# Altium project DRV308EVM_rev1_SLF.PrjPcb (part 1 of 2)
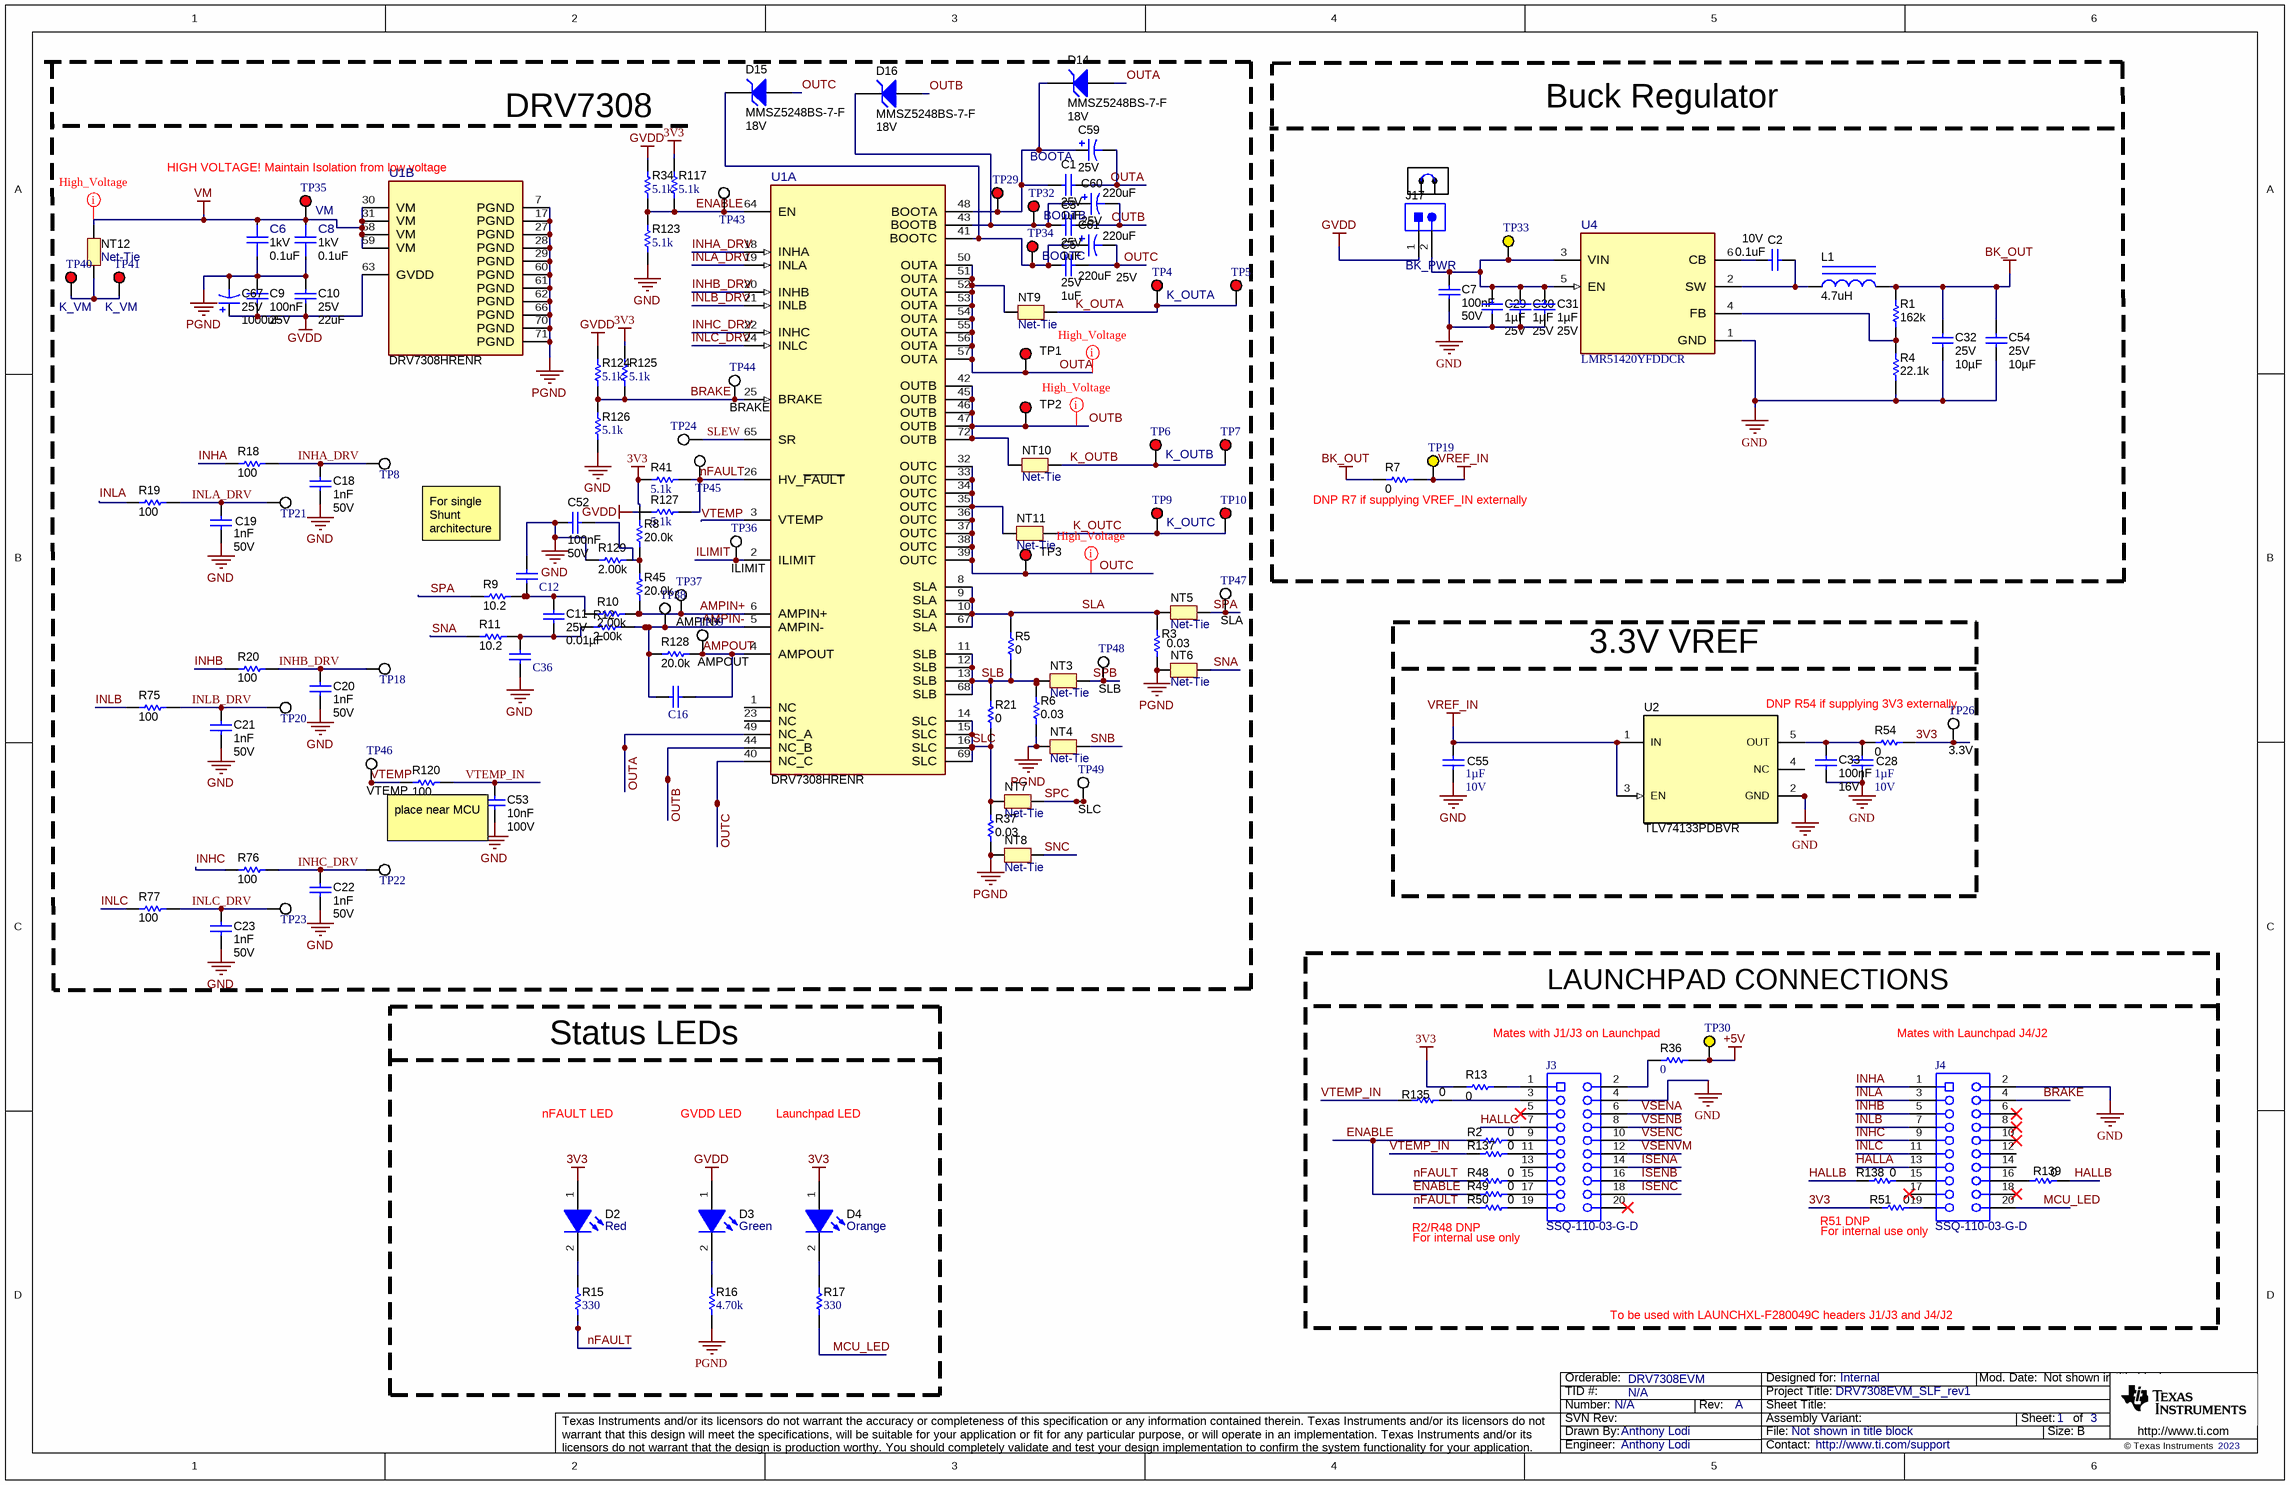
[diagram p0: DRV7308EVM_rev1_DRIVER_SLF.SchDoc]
CopyrightYear: 2023; DrawnBy: Anthony Lodi; EVM_orderable: DRV7308EVM; PCB_Layout: Anthony Lodi; PCB_Rev: A; PRJ_Customer: Internal; PRJ_Engineer: Anthony Lodi; PRJ_Number: N/A; PRJ_Title: DRV7308EVM_SLF_rev1; ProjectVariant: DRV7308EVM_rev1; SCH_Rev: A; TechSupport: http://www.ti.com/support; TID: N/A
3 sheets, 307 parts. Net scope: global (net labels, ports and power ports of the same name join across sheets).
Board file: DRV7308EVM_rev1_SLF.PcbDoc
Sheets:
  DRV7308EVM_rev1_DRIVER_SLF.SchDoc
  DRV7308EVM_rev1_HARDWARE_SLF.SchDoc
  DRV7308EVM_rev1_POWER_AND_CONNECTORS_SLF.SchDoc

## Sheet DRV7308EVM_rev1_DRIVER_SLF.SchDoc
size 431 x 279 mm; Date: Not shown in title block; ApprovedBy: Not shown in title block; CheckedBy: Not shown in title block; Author: Not shown in title block; CompanyName: Not shown in title block; DrawnBy: Anthony Lodi; Engineer: Not shown in title block; Organization: Not shown in title block; Address1: Not shown in title block; Address2: Not shown in title block; Address3: Not shown in title block; Address4: Not shown in title block; DocumentNumber: 1; Revision: Use project parameter SCH_Rev; SheetNumber: 1; SheetTotal: 3; PageSetup: Record=PageOptions¦CenterHorizontal=True¦CenterVertical=True¦PrintScale=1.00¦XCorrection=1.00¦YCorrection=1.00¦PrintKind=0¦BorderSize=5000000¦LeftOffset=0¦BottomOffset=0¦Orientation=2¦PaperLength=1000¦PaperWidth=1000¦Scale=100¦PaperSource=15¦PrintQuality=600¦MediaType=1¦DitherType=10¦PaperKind=Letter¦PrintScaleMode=1

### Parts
C1  VDC_V: 25V  ValueDisplayed: 1uF  [1206L]  (hidden comment: 12063C105KAT2A)
C2  VDC_V: 10V  ValueDisplayed: 0.1uF  [0402L]  (hidden comment: CL05B104KP5NNNC)
C3  VDC_V: 25V  ValueDisplayed: 1uF  [1206L]  (hidden comment: 12063C105KAT2A)
C5  VDC_V: 25V  ValueDisplayed: 1uF  [1206L]  (hidden comment: 12063C105KAT2A)
C6  VDC_V: 1kV  ValueDisplayed: 0.1uF  [FP-VJ2225Y104KXGAT_2225-IPC_A]  (hidden comment: VJ2225Y104KXGAT)
C7  Cap_F: 100nF  VDC_V: 50V  [0603L]  (hidden comment: 885012206095)
C8  VDC_V: 1kV  ValueDisplayed: 0.1uF  [FP-VJ2225Y104KXGAT_2225-IPC_A]  (hidden comment: VJ2225Y104KXGAT)
C9  Cap_F: 100nF  VDC_V: 25V  [0805_HV]  (hidden comment: 08053C104KAT2A)
C10  VDC_V: 25V  ValueDisplayed: 22uF  [1210_270L]  (hidden comment: GRM32ER71E226KE15L)
C11  VDC_V: 25V  ValueDisplayed: 0.01µF  [0402L]  (hidden comment: CL05B103KA5NNNC)
C12  885012206003  [WCAP-CSGP_0603_L1.6W0.8H0.8_Reflow]  (value not drawn)
C16  885012206003  [WCAP-CSGP_0603_L1.6W0.8H0.8_Reflow]  (value not drawn)
C18  Cap_F: 1nF  VDC_V: 50V  [0603L]  (hidden comment: 885012206083)
C19  Cap_F: 1nF  VDC_V: 50V  [0603L]  (hidden comment: 885012206083)
C20  Cap_F: 1nF  VDC_V: 50V  [0603L]  (hidden comment: 885012206083)
C21  Cap_F: 1nF  VDC_V: 50V  [0603L]  (hidden comment: 885012206083)
C22  Cap_F: 1nF  VDC_V: 50V  [0603L]  (hidden comment: 885012206083)
C23  Cap_F: 1nF  VDC_V: 50V  [0603L]  (hidden comment: 885012206083)
C28  Cap_F: 1µF  VDC_V: 10V  [0603L]  (hidden comment: LMK107B7105KAHT)
C29  Cap_F: 1µF  VDC_V: 25V  [0603L]  (hidden comment: CGA3E1X7R1E105K080AC)
C30  Cap_F: 1µF  VDC_V: 25V  [0603L]  (hidden comment: CGA3E1X7R1E105K080AC)
C31  Cap_F: 1µF  VDC_V: 25V  [0603L]  (hidden comment: CGA3E1X7R1E105K080AC)
C32  VDC_V: 25V  ValueDisplayed: 10µF  [1206_180L]  (hidden comment: C3216X7R1E106K160AB)
C33  Cap_F: 100nF  VDC_V: 16V  [0603L]  (hidden comment: EMK107B7104KA-T)
C36  885012206003  [WCAP-CSGP_0603_L1.6W0.8H0.8_Reflow]  (value not drawn)
C52  Cap_F: 100nF  VDC_V: 50V  [0603L]  (hidden comment: 885012206095)
C53  Cap_F: 10nF  VDC_V: 100V  [0603L]  (hidden comment: 06031C103JAT2A)
C54  VDC_V: 25V  ValueDisplayed: 10µF  [1206_180L]  (hidden comment: C3216X7R1E106K160AB)
C55  Cap_F: 1µF  VDC_V: 10V  [0603L]  (hidden comment: LMK107B7105KAHT)
C59  VDC_V: 25V  ValueDisplayed: 220uF  [BT_1000x1250]  (hidden comment: UBT1E221MPD1TD)
C60  VDC_V: 25V  ValueDisplayed: 220uF  [BT_1000x1250]  (hidden comment: UBT1E221MPD1TD)
C61  VDC_V: 25V  ValueDisplayed: 220uF  [BT_1000x1250]  (hidden comment: UBT1E221MPD1TD)
C67  VDC_V: 25V  ValueDisplayed: 1000uF  [Chemi-Con_1000x2000]  (hidden comment: EKMG250ELL102MJ20S)
D2  value Red  [LED_LTST-C170_Red]  (hidden comment: LTST-C170KRKT)
D3  value Green  [LTST-C170KGKT_Green]  (hidden comment: GVDD_LED)
D4  value Orange  [LTST-C170KFKT_Orange]  (hidden comment: MCU_LED)
D14  MMSZ5248BS-7-F  value 18V  [SOD-323]
D15  MMSZ5248BS-7-F  value 18V  [SOD-323]
D16  MMSZ5248BS-7-F  value 18V  [SOD-323]
J3  SSQ-110-03-G-D  [Samtec_SSQ-110-03-x-D]
J4  SSQ-110-03-G-D  [Samtec_SSQ-110-03-x-D]
J17  BK_PWR  [TSW-102-07-G-S]
L1  ValueDisplayed: 4.7uH  [WE-MAIA_3015]  (hidden comment: 78438335047)
NT3  Net-Tie  [Net-Tie_10mil]  (net tie, no BOM)
NT4  Net-Tie  [Net-Tie_10mil]  (net tie, no BOM)
NT5  Net-Tie  [Net-Tie_10mil]  (net tie, no BOM)
NT6  Net-Tie  [Net-Tie_10mil]  (net tie, no BOM)
NT7  Net-Tie  [Net-Tie_10mil]  (net tie, no BOM)
NT8  Net-Tie  [Net-Tie_10mil]  (net tie, no BOM)
NT9  Net-Tie  [Net-Tie_10milWide_30milLong]  (net tie, no BOM)
NT10  Net-Tie  [Net-Tie_10milWide_30milLong]  (net tie, no BOM)
NT11  Net-Tie  [Net-Tie_10milWide_30milLong]  (net tie, no BOM)
NT12  Net-Tie  [Net-Tie_10milWide_30milLong]  (net tie, no BOM)
R1  ValueDisplayed: 162k  [0603L]  (hidden comment: CRCW0603162KFKEA)
R2  ValueDisplayed: 0  [0603L]  (hidden comment: ERJ-3GEY0R00V)
R3  ValueDisplayed: 0.03  [1206L]  (hidden comment: CSR1206FK30L0)
R4  ValueDisplayed: 22.1k  [0603L]  (hidden comment: RT0603DRE0722K1L)
R5  ValueDisplayed: 0  [0805L]  (hidden comment: ERJ-6GEY0R00V)
R6  ValueDisplayed: 0.03  [1206L]  (hidden comment: CSR1206FK30L0)
R7  ValueDisplayed: 0  [0805L]  (hidden comment: ERJ-6GEY0R00V)
R8  ValueDisplayed: 20.0k  [0402L]  (hidden comment: CRCW040220K0FKED)
R9  ValueDisplayed: 10.2  [0402L]  (hidden comment: CRCW040210R2FKED)
R10  ValueDisplayed: 2.00k  [0402L]  (hidden comment: ERJ-2RKF2001X)
R11  ValueDisplayed: 10.2  [0402L]  (hidden comment: CRCW040210R2FKED)
R12  ValueDisplayed: 2.00k  [0402L]  (hidden comment: ERJ-2RKF2001X)
R13  ValueDisplayed: 0  [0805L]  (hidden comment: ERJ-6GEY0R00V)
R15  ValueDisplayed: 330  [0603L]  (hidden comment: ERA3AEB331V)
R16  ValueDisplayed: 4.70k  [0603L]  (hidden comment: RT0603BRD074K7L)
R17  ValueDisplayed: 330  [0603L]  (hidden comment: ERA3AEB331V)
R18  ValueDisplayed: 100  [0603L]  (hidden comment: RC0603FR-07100RL)
R19  ValueDisplayed: 100  [0603L]  (hidden comment: RC0603FR-07100RL)
R20  ValueDisplayed: 100  [0603L]  (hidden comment: RC0603FR-07100RL)
R21  ValueDisplayed: 0  [0805L]  (hidden comment: ERJ-6GEY0R00V)
R34  ValueDisplayed: 5.1k  [0603L]  (hidden comment: CRCW06035K10JNEA)
R36  ValueDisplayed: 0  [0805L]  (hidden comment: ERJ-6GEY0R00V)
R37  ValueDisplayed: 0.03  [1206L]  (hidden comment: CSR1206FK30L0)
R41  ValueDisplayed: 5.1k  [0603L]  (hidden comment: CRCW06035K10JNEA)
R45  ValueDisplayed: 20.0k  [0402L]  (hidden comment: CRCW040220K0FKED)
R48  ValueDisplayed: 0  [0603L]  (hidden comment: ERJ-3GEY0R00V)
R49  ValueDisplayed: 0  [0603L]  (hidden comment: ERJ-3GEY0R00V)
R50  ValueDisplayed: 0  [0603L]  (hidden comment: ERJ-3GEY0R00V)
R51  ValueDisplayed: 0  [0603L]  (hidden comment: ERJ-3GEY0R00V)
R54  ValueDisplayed: 0  [0603L]  (hidden comment: ERJ-3GEY0R00V)
R75  ValueDisplayed: 100  [0603L]  (hidden comment: RC0603FR-07100RL)
R76  ValueDisplayed: 100  [0603L]  (hidden comment: RC0603FR-07100RL)
R77  ValueDisplayed: 100  [0603L]  (hidden comment: RC0603FR-07100RL)
R117  ValueDisplayed: 5.1k  [0603L]  (hidden comment: CRCW06035K10JNEA)
R120  ValueDisplayed: 100  [0603L]  (hidden comment: RC0603FR-07100RL)
R123  ValueDisplayed: 5.1k  [0603L]  (hidden comment: CRCW06035K10JNEA)
R124  ValueDisplayed: 5.1k  [0603L]  (hidden comment: CRCW06035K10JNEA)
R125  ValueDisplayed: 5.1k  [0603L]  (hidden comment: CRCW06035K10JNEA)
R126  ValueDisplayed: 5.1k  [0603L]  (hidden comment: CRCW06035K10JNEA)
R127  ValueDisplayed: 5.1k  [0603L]  (hidden comment: CRCW06035K10JNEA)
R128  ValueDisplayed: 20.0k  [0402L]  (hidden comment: CRCW040220K0FKED)
R129  ValueDisplayed: 2.00k  [0402L]  (hidden comment: ERJ-2RKF2001X)
R135  ValueDisplayed: 0  [0603L]  (hidden comment: ERJ-3GEY0R00V)
R137  ValueDisplayed: 0  [0603L]  (hidden comment: ERJ-3GEY0R00V)
R138  ValueDisplayed: 0  [0603L]  (hidden comment: ERJ-3GEY0R00V)
R139  ValueDisplayed: 0  [0603L]  (hidden comment: ERJ-3GEY0R00V)
SH-J2  SNT-100-BK-G  [SNT-100-BK-G]  (value not drawn)
TP1  OUTA  [Keystone5000]  (value not drawn)
TP2  OUTB  [Keystone5000]  (value not drawn)
TP3  OUTC  [Keystone5000]  (value not drawn)
TP4  K_OUTA  [Keystone5000]
TP5  K_LS_D  [Keystone5000]  (value not drawn)
TP6  K_OUTB  [Keystone5000]
TP7  K_OUTB  [Keystone5000]  (value not drawn)
TP8  INHA  [Testpoint_Keystone_Miniature]  (value not drawn)
TP9  K_OUTC  [Keystone5000]
TP10  K_LS_D  [Keystone5000]  (value not drawn)
TP18  INHB  [Testpoint_Keystone_Miniature]  (value not drawn)
TP19  LDO_IN  [Keystone5009]  (value not drawn)
TP20  INLB  [Testpoint_Keystone_Miniature]  (value not drawn)
TP21  INLA  [Testpoint_Keystone_Miniature]  (value not drawn)
TP22  INHC  [Testpoint_Keystone_Miniature]  (value not drawn)
TP23  INLC  [Testpoint_Keystone_Miniature]  (value not drawn)
TP24  SLEW  [Testpoint_Keystone_Miniature]  (value not drawn)
TP26  3.3V  [Keystone5002]
TP29  BOOTA  [Keystone5000]
TP30  +5V  [Keystone5009]  (value not drawn)
TP32  BOOTB  [Keystone5000]
TP33  BK_PWR  [Keystone5009]  (value not drawn)
TP34  BOOTC  [Keystone5000]
TP35  VM  [Keystone5000]
TP36  ILIMIT  [Keystone5002]
TP37  AMPIN+  [Keystone5002]
TP38  AMPIN-  [Keystone5002]  (value not drawn)
TP39  AMPOUT  [Keystone5002]
TP40  K_VM  [Keystone5000]
TP41  K_VM  [Keystone5000]
TP43  ENABLE  [Testpoint_Keystone_Miniature]  (value not drawn)
TP44  BRAKE  [Keystone5002]
TP45  nFAULT  [Testpoint_Keystone_Miniature]  (value not drawn)
TP46  VTEMP  [Keystone5002]
TP47  SLA  [Keystone5002]
TP48  SLB  [Keystone5002]
TP49  SLC  [Keystone5002]
U1  DRV7308HRENR  [REN0065A-MFG]  (parts A,B of 2)
U2  TLV74133PDBVR  [DBV0005A_N]
U4  LMR51420YFDDCR  [DDC0006A-MFG]

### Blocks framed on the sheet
Buck Regulator: C2 C7 C29-C32 C54 J17 L1 R1 R4 R7 SH-J2 TP19 TP33 U4
3.3V VREF: C28 C33 C55 R54 TP26 U2
LAUNCHPAD CONNECTIONS: J3 J4 R2 R13 R36 R48-R51 R135 R137-R139 TP30
Status LEDs: D2-D4 R15-R17

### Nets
3V3: D2.1(A) D4.1(A) R8.2 R13.1 R41.2 R51.1 R54.2 R117.1 R125.1 TP26.1
+5V: R36.2 TP30.1
BK_OUT: C32.1 C54.1 L1.2 R1.2 R7.1
GND: C7.2 C12.1 C18.2 C19.2 C20.2 C21.2 C22.2 C23.2 C28.2 C29.2 C30.2 C31.2 C32.2 C33.2 C36.2 C52.1 C53.2 C54.2 C55.2 J3.4 J4.2 R4.1 R123.1 R126.1 R129.1 U2.2(GND) U4.1(GND)
GVDD: C9.2 C10.2 C67.1(+) D3.1(A) J17.1 R34.1 R124.1 R127.1 U1.63(GVDD)
PGND: C6.1 C8.1 C9.1 C10.1 C67.2(-) NT4.1 NT6.1 NT8.1 R3.1 R6.1 R16.1 R37.1 U1.7(PGND) U1.17(PGND) U1.27(PGND) U1.28(PGND) U1.29(PGND) U1.60(PGND) U1.61(PGND) U1.62(PGND) U1.66(PGND) U1.70(PGND) U1.71(PGND)
VM: C6.2 C8.2 NT12.2 TP35.1 U1.30(VM) U1.31(VM) U1.58(VM) U1.59(VM)
VREF_IN: C55.1 R7.2 TP19.1 U2.1(IN) U2.3(EN)
AMPIN+: R10.2 R45.1 TP37.1 U1.6(AMPIN+)
AMPIN-: C16.1 R12.2 R128.1 TP38.1 U1.5(AMPIN-)
AMPOUT: C16.2 R128.2 TP39.1 U1.4(AMPOUT)
BRAKE: J4.4 R124.2 R125.2 R126.2 TP44.1 U1.25(BRAKE)
ENABLE: R2.1 R34.2 R49.1 R117.2 R123.2 TP43.1 U1.64(EN)
HALLA: J4.13
HALLB: R138.1 R139.2
HALLC: J3.7
ILIMIT: TP36.1 U1.2(ILIMIT)
INHA: J4.1 R18.1
INHA_DRV: C18.1 R18.2 TP8.1 U1.18(INHA)
INHB: J4.5 R20.1
INHB_DRV: C20.1 R20.2 TP18.1 U1.20(INHB)
INHC: J4.9 R76.1
INHC_DRV: C22.1 R76.2 TP22.1 U1.22(INHC)
INLA: J4.3 R19.1
INLA_DRV: C19.1 R19.2 TP21.1 U1.19(INLA)
INLB: J4.7 R75.1
INLB_DRV: C21.1 R75.2 TP20.1 U1.21(INLB)
INLC: J4.11 R77.1
INLC_DRV: C23.1 R77.2 TP23.1 U1.24(INLC)
ISENA: J3.14
ISENB: J3.16
ISENC: J3.18
K_OUTA: NT9.2 TP4.1 TP5.1
K_OUTB: NT10.2 TP6.1 TP7.1
K_OUTC: NT11.2 TP9.1 TP10.1
MCU_LED: J4.20 R17.1
nFAULT: R15.1 R41.1 R48.1 R50.1 R127.2 TP45.1 U1.26(HV_~{FAULT})
OUTA: C1.1 C59.2(-) D14.2(A) NT9.1 TP1.1 U1.49(NC_A) U1.50(OUTA) U1.51(OUTA) U1.52(OUTA) U1.53(OUTA) U1.54(OUTA) U1.55(OUTA) U1.56(OUTA) U1.57(OUTA)
OUTB: C3.1 C60.2(-) D16.2(A) NT10.1 TP2.1 U1.42(OUTB) U1.44(NC_B) U1.45(OUTB) U1.46(OUTB) U1.47(OUTB) U1.72(OUTB)
OUTC: C5.1 C61.2(-) D15.2(A) NT11.1 TP3.1 U1.32(OUTC) U1.33(OUTC) U1.34(OUTC) U1.35(OUTC) U1.36(OUTC) U1.37(OUTC) U1.38(OUTC) U1.39(OUTC) U1.40(NC_C)
SLA: NT5.1 R3.2 R5.2 U1.8(SLA) U1.9(SLA) U1.10(SLA) U1.67(SLA)
SLB: NT3.1 R5.1 R6.2 R21.2 U1.11(SLB) U1.12(SLB) U1.13(SLB) U1.68(SLB)
SLC: NT7.1 R21.1 R37.2 U1.14(SLC) U1.15(SLC) U1.16(SLC) U1.69(SLC)
SLEW: TP24.1 U1.65(SR)
SNA: NT6.2 R11.1
SNB: NT4.2
SNC: NT8.2
SPA: NT5.2 R9.1 TP47.1
SPB: NT3.2 TP48.1
SPC: NT7.2 TP49.1
VSENA: J3.6
VSENB: J3.8
VSENC: J3.10
VSENVM: J3.12
VTEMP: R120.1 TP46.1 U1.3(VTEMP)
VTEMP_IN: C53.1 R120.2 R135.1 R137.1
NetC1_2: C1.2 C59.1(+) D14.1(K) TP29.1 U1.48(BOOTA)
NetC2_1: C2.1 L1.1 U4.2(SW)
NetC2_2: C2.2 U4.6(CB)
NetC3_2: C3.2 C60.1(+) D16.1(K) TP32.1 U1.43(BOOTB)
NetC5_2: C5.2 C61.1(+) D15.1(K) TP34.1 U1.41(BOOTC)
NetC7_1: C7.1 C29.1 C30.1 C31.1 J17.2 TP33.1 U4.3(VIN) U4.5(EN)
NetC11_1: C11.1 C12.2 R9.2 R10.1
NetC11_2: C11.2 C36.1 R11.2 R12.1
NetC28_1: C28.1 C33.1 R54.1 U2.5(OUT)
NetC52_2: C52.2 R8.1 R45.2 R129.2
NetD2_2: D2.2(K) R15.2
NetD3_2: D3.2(K) R16.2
NetD4_2: D4.2(K) R17.2
NetJ3_1: J3.1 R13.2
NetJ3_2: J3.2 R36.1
NetJ3_3: J3.3 R135.2
NetJ3_9: J3.9 R2.2
NetJ3_11: J3.11 R137.2
NetJ3_15: J3.15 R48.2
NetJ3_17: J3.17 R49.2
NetJ3_19: J3.19 R50.2
NetJ4_15: J4.15 R138.2
NetJ4_16: J4.16 R139.1
NetJ4_19: J4.19 R51.2
NetNT12_1: NT12.1 TP40.1 TP41.1
NetR1_1: R1.1 R4.2 U4.4(FB)

Not connected (* = marked no-connect by the designer): J3 5* 13 20*; J4 6* 8* 10* 12 14 17* 18*; U1 1(NC) 23(NC); U2 4(NC)

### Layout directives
net class High_Voltage: (no net found under the mark), OUTA, OUTC, VM

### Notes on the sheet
- HIGH VOLTAGE! Maintain Isolation from low voltage
- DRV7308
- (near R7) DNP R7 if supplying VREF_IN externally
- For single Shunt architecture
- DNP R54 if supplying 3V3 externally
- place near MCU
- (near R36) Mates with J1/J3 on Launchpad
- (near J4) Mates with Launchpad J4/J2
- nFAULT LED
- GVDD LED
- Launchpad LED
- (near R50) R2/R48 DNP
- For internal use only
- (near R51) R51 DNP
- To be used with LAUNCHXL-F280049C headers J1/J3 and J4/J2

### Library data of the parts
C1 C3 C5 = CMP-0008509-2: CAP, CERM, 1 uF, 25 V, +/- 10%, X7R, 1206; Manufacturer: AVX; TaMin_C: -55°C; ESR_ohm: 13m; Polarized: N; SizeAreaWB_mm2: 10.92; Value1: 0.013 ohm; U/M: EA; Value: 1uF; TaMax_C: 125°C; SizeZ_mm: 1.35; SizeX_mm: 3.2; SizeY_mm: 1.6; Cap_Case: 1206; SizeArea_mm2: 5.12; Cap_F: 1µF; AEC Category: Q200
C2 = CMP-0006343-2: CAP, CERM, 0.1 uF, 10 V, +/- 10%, X7R, 0402; Manufacturer: Samsung Electro-Mechanics; TaMin_C: -55°C; Polarized: N; SizeAreaWB_mm2: 3; Value1: Unknown; U/M: EA; Value: 0.1uF; TaMax_C: 125°C; SizeZ_mm: 0.6; SizeX_mm: 1; SizeY_mm: 0.5; Cap_Case: 0402; Cap_F: 100nF; AEC Category: Q200
C6 C8 = CMP-0097628-1: 2225 0.1 uF 1 kV ±10 % Tolerance X7R SMT Multilayer Ceramic Chip Capacitor; Manufacturer: Vishay Vitramon; Tolerance_%: 10%; Cap_F: 100nF; Value: 100nF; SizeZ_mm: 2.18mm; TempCo: 15%; AEC Qualified: No
C7 C52 = CMP-0006837-2: CAP, CERM, 0.1 uF, 50 V, +/- 10%, X7R, 0603; Manufacturer: Wurth Elektronik; TaMin_C: -55°C; Polarized: N; SizeAreaWB_mm2: 4.68; Value1: Unknown; U/M: EA; Value: 0.1uF; TaMax_C: 125°C; SizeZ_mm: 1; SizeX_mm: 1.6; SizeY_mm: 0.8; Cap_Case: 0603; SizeArea_mm2: 1.28; AEC Category: Q200
C9 = CMP-0007567-1: CAP, CERM, 0.1 uF, 25 V, +/- 10%, X7R, 0805; Manufacturer: AVX; TaMin_C: -55°C; ESR_ohm: 0.28; Polarized: N; SizeAreaWB_mm2: 6.75; Value1: 0.28 ohm; U/M: EA; Value: 0.1uF; TaMax_C: 125°C; SizeZ_mm: 1.45; SizeX_mm: 2; SizeY_mm: 1.25; Cap_Case: 0805; SizeArea_mm2: 2.5; AEC Category: Q200
C10 = CMP-0009224-2: CAP, CERM, 22 uF, 25 V, +/- 10%, X7R, 1210; Manufacturer: MuRata; TaMin_C: -55°C; Polarized: N; SizeAreaWB_mm2: 14.7; Value1: Unknown; U/M: EA; Value: 22uF; TaMax_C: 125°C; SizeZ_mm: 2.7; SizeX_mm: 3.2; SizeY_mm: 2.5; Cap_Case: 1210; SizeArea_mm2: 8; Cap_F: 22µF; AEC Category: Q200
C11 = CMP-0860561-1: CAP, CERM, 0.01 µF, 25 V,+/- 10%, X7R, 0402; Manufacturer: Samsung Electro-Mechanics; U/M: EA; SizeArea_mm2: 0.5; Value: 0.01uF; TaMin_C: -55°C; SizeZ_mm: 0.6; Polarized: N; SizeX_mm: 1; TaMax_C: 125°C; SizeAreaWB_mm2: 3; Cap_Case: 0402; Cap_F: 10nF; AEC Category: Q200
C12 C16 C36 = CMP-0104643-1: WCAP-CSGP Multilayer Ceramic Chip Capacitor, General Purpose, size 0603, X7R, 100pF, 10VDC; Manufacturer: Wurth Elektronik; Capacitance Tolerance: +/-10%; Case/Size Code: 0603; Dissipation Factor: 5%; Insulation Resistance: 10GOhm; Rated Voltage (DC): 10V; Technical Reference: X7R0603101K010DFCT10000
C18-C23 = CMP-0064933-2: CAP, CERM, 1000 pF, 50 V,+/- 10%, X7R, 0603; Manufacturer: Wurth Elektronik; TaMin_C: -55°C; Polarized: N; SizeAreaWB_mm2: 4.68; Value1: Unknown; U/M: EA; Value: 1000pF; TaMax_C: 125°C; SizeZ_mm: 1; SizeX_mm: 1.6; SizeY_mm: 0.8; Cap_Case: 0603; SizeArea_mm2: 1.28; AEC Category: Q200
C28 C55 = CMP-0007505-3: CAP, CERM, 1 uF, 10 V, +/- 10%, X7R, AEC-Q200 Grade 1, 0603; Manufacturer: Taiyo Yuden; TaMin_C: -55°C; Polarized: N; SizeAreaWB_mm2: 4.68; Value1: Unknown; U/M: EA; Value: 1uF; TaMax_C: 125°C; SizeZ_mm: 1; SizeX_mm: 1.6; SizeY_mm: 0.8; Cap_Case: 0603; SizeArea_mm2: 1.28; AEC Qualified: Y; AEC Category: Q200
C29-C31 = CMP-0076705-1: CAP, CERM, 1 µF, 25 V,+/- 10%, X7R, AEC-Q200 Grade 1, 0603; Manufacturer: TDK; SizeAreaWB_mm2: 4.68; SizeArea_mm2: 1.28; AEC Qualified: Y; AEC Category: Q200; Value: 1uF; TaMax_C: 125°C; SizeZ_mm: 1.0; AEC Grade: 1; Polarized: N; TaMin_C: -55°C; SizeY_mm: 0.8; U/M: EA; SizeX_mm: 1.6; Cap_Case: 1.6x0.8x0.8mm
C32 C54 = CMP-0080740-1: CAP, CERM, 10 µF, 25 V,+/- 10%, X7R, 1206; Manufacturer: TDK; SizeAreaWB_mm2: 10.92; SizeArea_mm2: 5.12; AEC Qualified: N; AEC Category: Q200; Value: 10uF; TaMax_C: 125°C; SizeZ_mm: 1.8; TaMin_C: -55°C; SizeY_mm: 1.6; U/M: EA; SizeX_mm: 3.2; Cap_Case: 1206
C33 = CMP-0007119-4: CAP, CERM, 0.1 uF, 16 V, +/- 10%, X7R, 0603; Manufacturer: Taiyo Yuden; TaMin_C: -55°C; Polarized: N; SizeAreaWB_mm2: 4.68; Value1: Unknown; U/M: EA; Value: 0.1uF; TaMax_C: 125°C; SizeZ_mm: 1; SizeX_mm: 1.6; SizeY_mm: 0.8; Cap_Case: 0603; SizeArea_mm2: 1.28; AEC Category: Q200
C53 = CMP-0006726-4: CAP, CERM, 0.01 uF, 100 V, +/- 5%, X7R, 0603; Manufacturer: AVX; TaMin_C: -55°C; ESR_ohm: 0.098; Polarized: N; SizeAreaWB_mm2: 4.68; Value1: 0.098 ohm; U/M: EA; Value: 0.01uF; TaMax_C: 125°C; SizeZ_mm: 1; SizeX_mm: 1.6; SizeY_mm: 0.8; Cap_Case: 0603; SizeArea_mm2: 1.28; AEC Category: Q200
C59-C61 = CMP-0010527-1: CAP, AL, 220 uF, 25 V, +/- 20%, 0.1 ohm, TH; Manufacturer: Nichicon; TaMin_C: -40°C; ESR_ohm: 0.1; Polarized: Y; SizeAreaWB_mm2: 144; Value1: 0.1 ohm; U/M: EA; Value: 220uF; TaMax_C: 125°C; SizeZ_mm: 14.5; SizeX_mm: 10; Cap_Case: 10x12.5mm; SizeArea_mm2: 100; CompType: Capacitor; Cap_F: 220µF; IRMS_A: 680mA; AEC Category: Q200
C67 = CMP-0010362-1: CAP, AL, 1000 uF, 25 V, +/- 20%, TH; Manufacturer: Chemi-Con; TaMin_C: -55°C; Polarized: Y; SizeAreaWB_mm2: 144; Value1: Unknown; U/M: EA; Value: 1000uF; TaMax_C: 105°C; SizeZ_mm: 21.5; SizeX_mm: 10; Cap_Case: 10x20mm; SizeArea_mm2: 100; CompType: Capacitor; AEC Qualified: N; Cap_F: 1mF; IRMS_A: 680mA; AEC Category: Q200
D2 = CMP-0002829-1: LED, Red, SMD; Manufacturer: Lite-On; Io_A: 20mA; SizeAreaWB_mm2: 6.75; Value1: W; U/M: EA; SizeZ_mm: 1.2; SizeX_mm: 2; SizeY_mm: 1.25; Vf_V: 2V; SizeArea_mm2: 2.5; Type: AlInGaP
D3 = CMP-0002888-1: LED, Green, SMD; Manufacturer: Lite-On; PartNumber: LTST-C170KGKT; Io_A: 20mA; Value1: W; U/M: EA; Vf_V: 2V; Type: AlInGaP
D4 = CMP-0002890-1: LED, Orange, SMD; Manufacturer: Lite-On; PartNumber: LTST-C170KFKT; Io_A: 20mA; Value1: W; U/M: EA; Vf_V: 2V; Type: AlInGaP
D14-D16 = CMP-0005835-4: Diode, Zener, 18 V, 200 mW, SOD-323; Manufacturer: Diodes Inc.; Value1: 0.2W; SizeArea_mm2: 3.645; AEC Category: Q101; Power_W: 200mW; SizeAreaWB_mm2: 8.695; SizeY_mm: 1.35; RJA_CperW: 350; SizeZ_mm: 1; SizeX_mm: 2.7
J3 J4 = CMP-0075613-1: Receptacle, 2.54mm, 10x2, Gold, TH; Manufacturer: Samtec; Pitch_mm: 2.54; Cert_VDE: N; Gender: Female; Cert_CSA: Y; Current_A: 6.3A; Voltage_V: 550V; CT: True; Row_Count: 2; CompType: Socket Strip; CNHeader: False
J17 = CMP-0075405-3: Header, 100mil, 2x1, Gold, TH; Manufacturer: Samtec; Current_A: 6.3A; Green_Lifecycle: Active; Pitch_mm: 2.54; Cert_CSA: Y; Cert_VDE: N; Green_REACh: Passed; Row_Count: 1; Gender: Male; Voltage_V: 550V
L1 = CMP-0064361-1: Inductor, Shielded, Powdered Iron, 4.7 uH, 1.5 A, 0.162 ohm, AEC-Q200 Grade 1, SMD; Manufacturer: Wurth Elektronik; Isat: 2.8A @ 20% inductance drop; Irms: 1.5A @ 40C rise; SizeAreaWB_mm2: 16; DCR_ohm: 0.162; Value: 4.7uH; Imax_A: 1.5A; SizeZ_mm: 1.5; SizeX_mm: 3; SizeArea_mm2: 9; Ind_H: 4.7µH; AEC Qualified: Y; AEC Grade: 1; AEC Category: Q200
NT3-NT12 = CMP-0078142-4: Single point connection between nets.
R1 = CMP-0022073-1: RES, 162 k, 1%, 0.1 W, 0603; Manufacturer: Vishay-Dale; Power_W: 100mW; TempCo: 100 ppm/C; U/M: EA; Value: 162k; EIA_Code: E96; SizeX_mm: 1.6; SizeY_mm: 0.8; SizeZ_mm: 1; Value2: 0.1W; SizeArea_mm2: 1.28; VDC_V: 75V; AEC Category: Q200
R2 R48-R51 R54 R135 R137-R139 = CMP-0025874-4: RES, 0, 5%, 0.1 W, AEC-Q200 Grade 0, 0603; Manufacturer: Panasonic; Power_W: 100mW; TempCo: 600 ppm/C; Value_Code: 0000; Value: 0; EIA_Code: E24; SizeX_mm: 1.6; SizeY_mm: 0.8; SizeZ_mm: 1; Value2: 0.1W; SizeArea_mm2: 1.28; AEC Qualified: Y; VDC_V: 50V; AEC Category: Q200; SizeAreaWB_mm2: 4.68
R3 R6 R37 = CMP-0017262-1: RES, 0.03, 1%, 0.5 W, 1206; Manufacturer: Stackpole Electronics Inc; Power_W: 500mW; TempCo: 100 ppm/C; Value_Code: R030; U/M: EA; Value: 0.03; EIA_Code: E96; SizeX_mm: 3.2; SizeY_mm: 1.6; SizeZ_mm: 1.35; Value2: 0.5W; SizeArea_mm2: 5.12; AEC Category: Q200
R4 = CMP-0024951-1: RES, 22.1 k, 0.5%, 0.1 W, 0603; Manufacturer: Yageo America; Power_W: 100mW; TempCo: 50 ppm/C; Value_Code: 22k1; U/M: EA; Value: 22.1k; EIA_Code: E192; SizeX_mm: 1.6; SizeY_mm: 0.8; SizeZ_mm: 1; Value2: 0.1W; SizeArea_mm2: 1.28; VDC_V: 75V; AEC Category: Q200
R5 R21 = CMP-0020616-1: RES, 0, 5%, 0.125 W, 0805; Manufacturer: Panasonic; Power_W: 125mW; TempCo: 600 ppm/C; Value_Code: 0000; U/M: EA; Value: 0; EIA_Code: E24; SizeX_mm: 2; SizeY_mm: 1.25; SizeZ_mm: 1.45; Value2: 0.125W; SizeArea_mm2: 2.5; VDC_V: 150V; AEC Category: Q200
R7 R13 R36 = CMP-0020616-3: RES, 0, 5%, 0.125 W, AEC-Q200 Grade 0, 0805; Manufacturer: Panasonic; Power_W: 125mW; TempCo: 600 ppm/C; Value_Code: 0000; Value: 0; EIA_Code: E24; SizeX_mm: 2; SizeY_mm: 1.25; SizeZ_mm: 1.45; Value2: 0.125W; SizeArea_mm2: 2.5; AEC Qualified: Y; VDC_V: 150V; AEC Category: Q200; SizeAreaWB_mm2: 6.75
R8 R45 R128 = CMP-0026162-2: RES, 20.0 k, 1%, 0.063 W, AEC-Q200 Grade 0, 0402; Manufacturer: Vishay-Dale; Power_W: 63mW; TempCo: 100 ppm/C; Value_Code: 20k0; Value: 20.0k; EIA_Code: E96; Res_ohm: 20k; SizeX_mm: 1; SizeY_mm: 0.5; SizeZ_mm: 0.6; Value2: 0.063W; AEC Qualified: Y; VDC_V: 50V; AEC Category: Q200; AEC Grade: 0
R9 R11 = CMP-0025964-3: RES, 10.2, 1%, 0.063 W, AEC-Q200 Grade 0, 0402; Manufacturer: Vishay-Dale; Power_W: 63mW; TempCo: 100 ppm/C; Value_Code: 10R2; Value: 10.2; EIA_Code: E96; SizeX_mm: 1; SizeY_mm: 0.5; SizeZ_mm: 0.6; Value2: 0.063W; AEC Qualified: Y; VDC_V: 50V; AEC Category: Q200; AEC Grade: 0
R10 R12 R129 = CMP-0026676-1: RES, 2.00 k, 1%, 0.1 W, AEC-Q200 Grade 0, 0402; Manufacturer: Panasonic; Power_W: 100mW; TempCo: 100 ppm/C; Value_Code: 2k00; U/M: EA; Value: 2.00k; EIA_Code: E96; Res_ohm: 2k; SizeX_mm: 1; SizeY_mm: 0.5; SizeZ_mm: 0.6; Value2: 0.1W; AEC Qualified: Y; VDC_V: 50V; AEC Grade: 0; AEC Category: Q200
R15 R17 = CMP-0078582-1: RES, 330, 0.1%, 0.1 W, AEC-Q200 Grade 0, 0603; Manufacturer: Panasonic; Power_W: 100mW; TempCo: 25 ppm/C; Value_Code: 330R; Value: 330; SizeX_mm: 1.6; SizeY_mm: 0.8; SizeZ_mm: 1; Value2: 0.1W; SizeArea_mm2: 1.28; AEC Qualified: Y; AEC Grade: 0; AEC Category: Q200
R16 = CMP-0024300-2: RES, 4.70 k, 0.1%, 0.1 W, 0603; Manufacturer: Yageo America; Power_W: 100mW; TempCo: 25 ppm/C; Value_Code: 4k70; U/M: EA; Value: 4.70k; EIA_Code: E192; Res_ohm: 4.7k; SizeX_mm: 1.6; SizeY_mm: 0.8; SizeZ_mm: 1; Value2: 0.1W; SizeArea_mm2: 1.28; VDC_V: 75V; AEC Category: Q200
R18-R20 R75-R77 R120 = CMP-0022736-4: RES, 100, 1%, 0.1 W, 0603; Manufacturer: Yageo; Power_W: 100mW; TempCo: 100 ppm/C; Value_Code: 100R; Value: 100; EIA_Code: E96; SizeX_mm: 1.6; SizeY_mm: 0.8; SizeZ_mm: 1; Value2: 0.1W; SizeArea_mm2: 1.28; AEC Qualified: N; VDC_V: 75V; AEC Category: Q200; SizeAreaWB_mm2: 4.68
R34 R41 R117 R123-R127 = CMP-0025830-1: RES, 5.1 k, 5%, 0.1 W, 0603; Manufacturer: Vishay-Dale; Power_W: 100mW; TempCo: 200 ppm/C; Value_Code: 5k10; U/M: EA; Value: 5.1k; EIA_Code: E24; SizeX_mm: 1.6; SizeY_mm: 0.8; SizeZ_mm: 1; Value2: 0.1W; SizeArea_mm2: 1.28; VDC_V: 75V; AEC Category: Q200
SH-J2 = CMP-0003623-3: Shunt, 100mil, Gold plated, Black; Alternate PartNumber: 969102-0000-DA; Manufacturer: Samtec; Alternate Manufacturer: 3M; Value: 1x2
TP1-TP3 = CMP-0055137-1: Test Point, Miniature, Red, TH; PartNumber: 5000; Manufacturer: Keystone; ContactFinish: Silver; CNHeader: FALSE; CT: TRUE; Green_Lifecycle: Active; Green_REACh: Passed
TP4-TP7 TP9 TP10 TP29 TP32 TP34 TP35 TP40 TP41 = CMP-0055137-2: Test Point, Miniature, Red, TH; Manufacturer: Keystone Electronics; Green_REACh: Passed; Green_Lifecycle: Active; ContactFinish: Silver; CNHeader: FALSE; CT: TRUE
TP8 TP18 TP20-TP24 TP43 TP45 = CMP-0055152-1: Test Point, Miniature, SMT; Manufacturer: Keystone; CNHeader: FALSE; Green_Lifecycle: Active; Green_REACh: Passed; CT: TRUE
TP19 TP30 TP33 = CMP-0055146-2: Test Point, Compact, Yellow, TH; Manufacturer: Keystone Electronics; Green_REACh: Passed; ContactFinish: Silver; CT: TRUE; CNHeader: FALSE; Green_Lifecycle: Active
TP26 TP36-TP39 TP44 TP46-TP49 = CMP-0055139-2: Test Point, Miniature, White, TH; Manufacturer: Keystone Electronics; ContactFinish: Silver; Green_REACh: Passed; CT: TRUE; Green_Lifecycle: Active; CNHeader: FALSE
U1 = CMP-0098388-1: Three-Phase, 650-V Integrated GaN FET Motor Driver, VQFN65; Manufacturer: Texas Instruments; SizeZ_mm: 1mm; AEC Qualified: No; Max Supply Voltage: 18.5V; Min Supply Voltage: 10.8V; Motor Type: Brushless DC; Nominal Supply Current: 1-5mA; Number Of Outputs: 3; Standoff Height: 0mm; Switching Frequency: 20kHz; TaMax_C: +100°C; TaMin_C: -40°C; TJmax_C: +125°C
U2 = CMP-0065093-2: Low-Dropout Regulator, DBV0005A (SOT-23-5); Manufacturer: Texas Instruments; SizeX_mm: 2.8; SizeY_mm: 2.9; CompType: IC; SizeZ_mm: 1.45; SizeArea_mm2: 8.12; SizeAreaWB_mm2: 14.82; U/M: EA
U4 = CMP-0094075-1: SIMPLE SWITCHER 4.5-V to 36-V, 2-A Buck Converter in SOT-23-6 Package; Manufacturer: Texas Instruments; Nominal Supply Current: 40-420uA; Output Voltage: 0.6-30.4V; TJmax_C: +150°C; Number Of Outputs: 1; Max Supply Voltage: 32V; Standoff Height: 0mm; AEC Qualified: No; Output Type: AdjustableProgrammable; SizeZ_mm: 1.1mm; Switching Frequency: 500kHz; Max Duty Cycle: 98%; Min Supply Voltage: 4.5V

## Sheet DRV7308EVM_rev1_HARDWARE_SLF.SchDoc
size 431 x 279 mm; Date: Not shown in title block; ApprovedBy: Not shown in title block; CheckedBy: Not shown in title block; Author: Not shown in title block; CompanyName: Not shown in title block; DrawnBy: Anthony Lodi; Engineer: Not shown in title block; Organization: Not shown in title block; Address1: Not shown in title block; Address2: Not shown in title block; Address3: Not shown in title block; Address4: Not shown in title block; DocumentNumber: 3; Revision: Use project parameter SCH_Rev; SheetNumber: 3; SheetTotal: 3; PageSetup: Record=PageOptions¦CenterHorizontal=True¦CenterVertical=True¦PrintScale=1.00¦XCorrection=1.00¦YCorrection=1.00¦PrintKind=0¦BorderSize=5000000¦LeftOffset=0¦BottomOffset=0¦Orientation=2¦PaperLength=1000¦PaperWidth=1000¦Scale=100¦PaperSource=15¦PrintQuality=600¦MediaType=1¦DitherType=10¦PaperKind=Letter¦PrintScaleMode=1
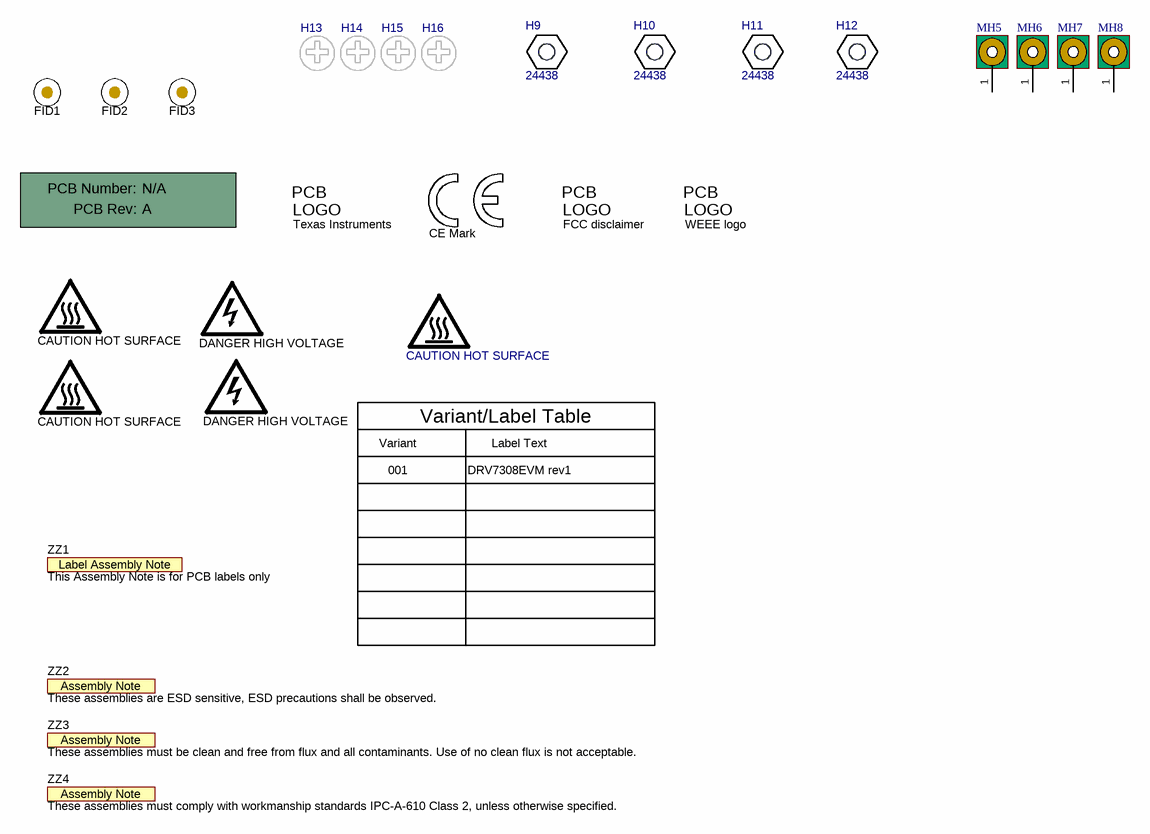
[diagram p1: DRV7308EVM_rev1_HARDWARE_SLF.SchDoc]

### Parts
!PCB1  Printed Circuit Board  (value not drawn)  (mechanical)
FID1  Fiducial  [Fiducial10-20]  (value not drawn)
FID2  Fiducial  [Fiducial10-20]  (value not drawn)
FID3  Fiducial  [Fiducial10-20]  (value not drawn)
H9  24438  [Keystone24438]
H10  24438  [Keystone24438]
H11  24438  [Keystone24438]
H12  24438  [Keystone24438]
H13  MPMS 003 0005 PH  [BuildingFastener_MPMS_003_0005_PH]  (value not drawn)
H14  MPMS 003 0005 PH  [BuildingFastener_MPMS_003_0005_PH]  (value not drawn)
H15  MPMS 003 0005 PH  [BuildingFastener_MPMS_003_0005_PH]  (value not drawn)
H16  MPMS 003 0005 PH  [BuildingFastener_MPMS_003_0005_PH]  (value not drawn)
LOGO  CAUTION HOT SURFACE  [IEC_HotSurface_Small]  (no BOM)
Logo1  CE Mark  [CE_Mark_5mm]  (no BOM)
Logo2  Texas Instruments  [TI_Stacked_Overlay_Small]  (no BOM)
Logo3  FCC disclaimer  [FCC_disclaimer]  (no BOM)
Logo4  WEEE logo  [WEEE_Minimum]  (no BOM)
LOGO5  CAUTION HOT SURFACE  [IEC_HotSurface_Small]  (no BOM)
LOGO6  DANGER HIGH VOLTAGE  [IEC_HighVoltage_Small]  (no BOM)
LOGO7  CAUTION HOT SURFACE  [IEC_HotSurface_Small]  (no BOM)
LOGO8  DANGER HIGH VOLTAGE  [IEC_HighVoltage_Small]  (no BOM)
MH5  MTG_Pads  [MTGP_M3_PanHead]  (value not drawn)  (no BOM)
MH6  MTG_Pads  [MTGP_M3_PanHead]  (value not drawn)  (no BOM)
MH7  MTG_Pads  [MTGP_M3_PanHead]  (value not drawn)  (no BOM)
MH8  MTG_Pads  [MTGP_M3_PanHead]  (value not drawn)  (no BOM)
ZZ1  This Assembly Note is for PCB labels only  [AssemblyNoteLabel]  (no BOM)
ZZ2  These assemblies are ESD sensitive, ESD precautions shall be observed.  [AssemblyNote]  (no BOM)
ZZ3  These assemblies must be clean and free from flux and all contaminants. Use of no clean flux is not acceptable.  [AssemblyNote]  (no BOM)
ZZ4  These assemblies must comply with workmanship standards IPC-A-610 Class 2, unless otherwise specified.  [AssemblyNote]  (no BOM)

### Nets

Not connected (* = marked no-connect by the designer): MH5 1; MH6 1; MH7 1; MH8 1

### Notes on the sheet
- Variant
- Variant/Label Table
- Label Text
- 001
- DRV7308EVM rev1

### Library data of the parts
!PCB1 = CMP-0003618-2: Manufacturer: Any
FID1-FID3 = CMP-0077181-1: Fiducial mark.  There is nothing to buy or mount.
H9-H12 = CMP-0003640-1: Standoff, Hex,25mm Length, M3, Aluminum; Manufacturer: Keystone; CompType: Hardware
H13-H16 = CMP-0003646-1: MACHINE SCREW PAN PHILLIPS M3 5mm; Manufacturer: B&F Fastener Supply; CompType: Hardware
LOGO = CMP-0074837-1: IEC 61010-1 Hot Surface Warning; SymbolCreator: a0412235
Logo1 = CMP-0074844-1: SymbolCreator: a0412235
Logo2 = CMP-0074838-1: Texas Instrument Corporate Signature; SymbolCreator: a0412235; Lib Reference: TI_Logo; Library Reference: Logo
Logo3 = CMP-0074847-1: FCC_disclaimer; Library Reference: Logo
Logo4 = CMP-0074769-1
LOGO5 LOGO7 = CMP-0074837-1: IEC 61010-1 Hot Surface Warning; SymbolCreator: a0412235; Lib Reference: IEC_HotSurface
LOGO6 LOGO8 = CMP-0074835-1: IEC 61010-1 High Voltage Warning; SymbolCreator: a0412235; Lib Reference: IEC_HighVoltage
MH5-MH8 = CMP-0078423-2: PCB Mounting Hole; Manufacturer: Any; Key: Mounting Hole (Metric) with Pads
ZZ1 = CMP-0003616-3
ZZ2 = CMP-0077236-1
ZZ3 = CMP-0077237-1
ZZ4 = CMP-0077238-1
